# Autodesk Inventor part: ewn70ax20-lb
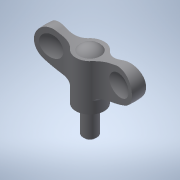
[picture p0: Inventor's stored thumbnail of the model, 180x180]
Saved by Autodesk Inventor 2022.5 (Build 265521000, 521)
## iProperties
Created: 2016-12
Part Number: ewn70ax20-lb
Material: 一般
Document SubType Name: Modeling
Designer: imaocorp
Density: 1 g/cm^3
Appearance: 既定
Author: imaocorp
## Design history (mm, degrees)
node "ewn70ax20-lb.x_t1"
node "ewn70ax20-lb"
node "Base1"
